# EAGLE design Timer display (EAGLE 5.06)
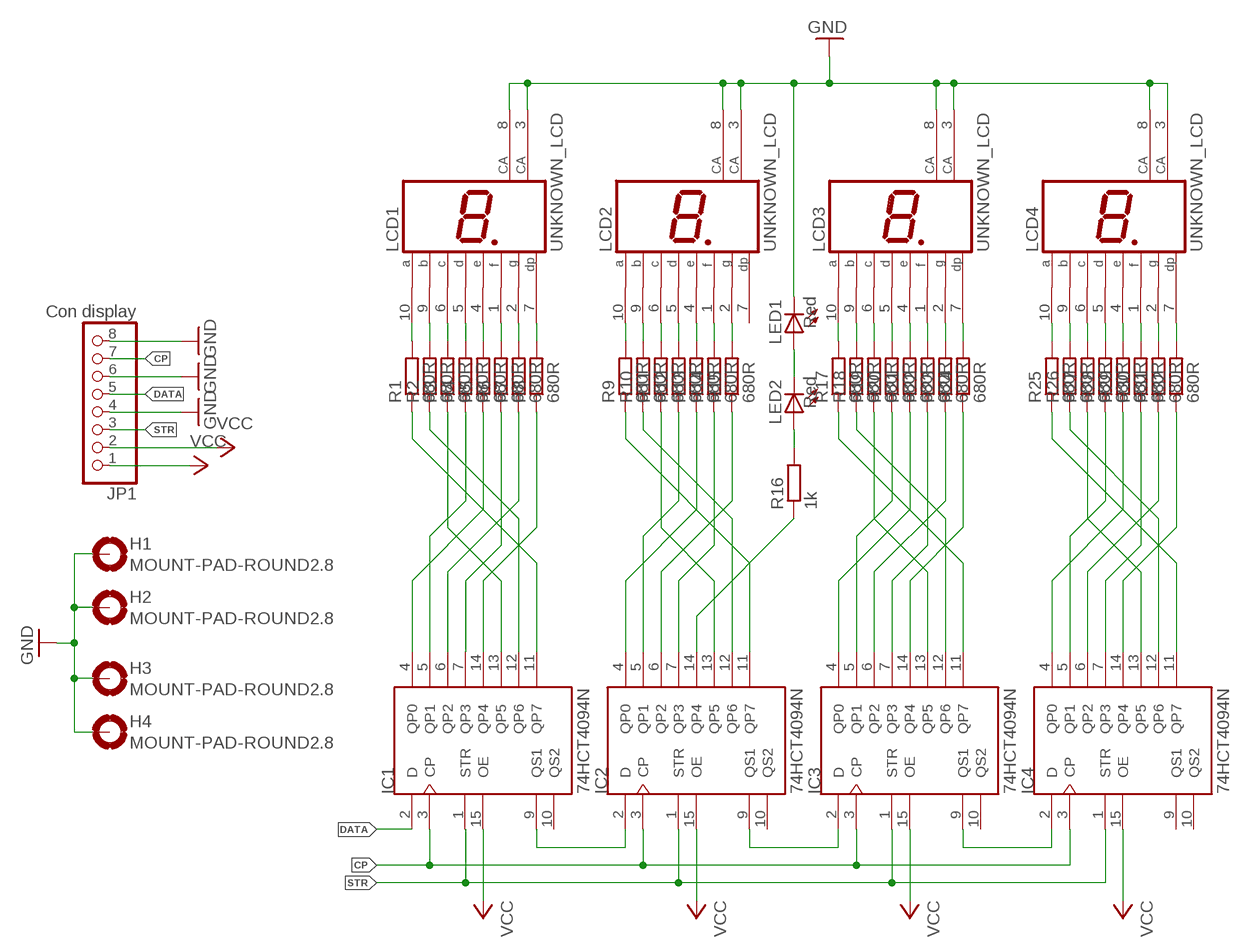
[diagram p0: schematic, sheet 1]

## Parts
H1  MOUNT-PAD-ROUND2.8  [2,8-PAD]
H2  MOUNT-PAD-ROUND2.8  [2,8-PAD]
H3  MOUNT-PAD-ROUND2.8  [2,8-PAD]
H4  MOUNT-PAD-ROUND2.8  [2,8-PAD]
IC1  74HCT4094N  [DIL16]
IC2  74HCT4094N  [DIL16]
IC3  74HCT4094N  [DIL16]
IC4  74HCT4094N  [DIL16]
JP1  Con display  PINHD-1X8  [1X08]
LCD1  UNKNOWN_LCD  [CA-MOJ]
LCD2  UNKNOWN_LCD  [CA-MOJ]
LCD3  UNKNOWN_LCD  [CA-MOJ]
LCD4  UNKNOWN_LCD  [CA-MOJ]
LED1  Red  LED3MM  [LED3MM]
LED2  Red  LED3MM  [LED3MM]
R1  680R  R-EU_R0805  [R0805]
R2  680R  R-EU_R0805  [R0805]
R3  680R  R-EU_R0805  [R0805]
R4  680R  R-EU_R0805  [R0805]
R5  680R  R-EU_R0805  [R0805]
R6  680R  R-EU_R0805  [R0805]
R7  680R  R-EU_R0805  [R0805]
R8  680R  R-EU_R0805  [R0805]
R9  680R  R-EU_R0805  [R0805]
R10  680R  R-EU_R0805  [R0805]
R11  680R  R-EU_R0805  [R0805]
R12  680R  R-EU_R0805  [R0805]
R13  680R  R-EU_R0805  [R0805]
R14  680R  R-EU_R0805  [R0805]
R15  680R  R-EU_R0805  [R0805]
R16  1k  R-EU_0207/10  [0207/10]
R17  680R  R-EU_R0805  [R0805]
R18  680R  R-EU_R0805  [R0805]
R19  680R  R-EU_R0805  [R0805]
R20  680R  R-EU_R0805  [R0805]
R21  680R  R-EU_R0805  [R0805]
R22  680R  R-EU_R0805  [R0805]
R23  680R  R-EU_R0805  [R0805]
R24  680R  R-EU_R0805  [R0805]
R25  680R  R-EU_R0805  [R0805]
R26  680R  R-EU_R0805  [R0805]
R27  680R  R-EU_R0805  [R0805]
R28  680R  R-EU_R0805  [R0805]
R29  680R  R-EU_R0805  [R0805]
R30  680R  R-EU_R0805  [R0805]
R31  680R  R-EU_R0805  [R0805]
R32  680R  R-EU_R0805  [R0805]

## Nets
CP: IC1.3(CP) IC2.3(CP) IC3.3(CP) IC4.3(CP) JP1.7
DATA: IC1.2(D) JP1.5
GND: H1.B2,8(MOUNT) H2.B2,8(MOUNT) H3.B2,8(MOUNT) H4.B2,8(MOUNT) JP1.4 JP1.6 JP1.8 LCD1.3(CA) LCD1.8(CA) LCD2.3(CA) LCD2.8(CA) LCD3.3(CA) LCD3.8(CA) LCD4.3(CA) LCD4.8(CA) LED1.K(C)
N$1: IC1.7(QP3) R6.1
N$2: LCD1.10(A) R1.2
N$3: LCD1.9(B) R2.2
N$4: LCD1.6(C) R3.2
N$5: LCD1.5(D) R4.2
N$6: LCD1.4(E) R5.2
N$7: LCD1.1(F) R6.2
N$8: LCD1.2(G) R7.2
N$9: LCD1.7(DP) R8.2
N$10: IC1.6(QP2) R7.1
N$11: IC1.4(QP0) R5.1
N$12: IC1.5(QP1) R4.1
N$13: IC1.11(QP7) R1.1
N$14: IC1.12(QP6) R2.1
N$15: IC1.14(QP4) R8.1
N$16: IC1.13(QP5) R3.1
N$17: IC2.11(QP7) R9.1
N$18: IC2.12(QP6) R10.1
N$19: IC2.13(QP5) R11.1
N$20: IC2.5(QP1) R12.1
N$21: IC2.4(QP0) R13.1
N$22: IC2.6(QP2) R15.1
N$23: IC2.7(QP3) R14.1
N$24: LED1.A LED2.K(C)
N$25: LED2.A R16.2
N$26: LCD2.2(G) R15.2
N$27: LCD2.1(F) R14.2
N$28: LCD2.4(E) R13.2
N$29: LCD2.5(D) R12.2
N$30: LCD2.6(C) R11.2
N$31: LCD2.9(B) R10.2
N$32: LCD2.10(A) R9.2
N$33: IC3.12(QP6) R18.1
N$34: IC3.11(QP7) R17.1
N$35: IC3.13(QP5) R19.1
N$36: IC3.5(QP1) R20.1
N$37: IC3.4(QP0) R21.1
N$38: IC3.6(QP2) R23.1
N$39: IC3.7(QP3) R22.1
N$40: IC3.14(QP4) R24.1
N$41: LCD3.10(A) R17.2
N$42: LCD3.9(B) R18.2
N$43: LCD3.6(C) R19.2
N$44: LCD3.5(D) R20.2
N$45: LCD3.4(E) R21.2
N$46: LCD3.1(F) R22.2
N$47: LCD3.2(G) R23.2
N$48: LCD3.7(DP) R24.2
N$49: LCD4.10(A) R25.2
N$50: LCD4.9(B) R26.2
N$51: LCD4.6(C) R27.2
N$52: LCD4.5(D) R28.2
N$53: LCD4.4(E) R29.2
N$54: LCD4.1(F) R30.2
N$55: LCD4.2(G) R31.2
N$56: LCD4.7(DP) R32.2
N$57: IC4.12(QP6) R26.1
N$58: IC4.11(QP7) R25.1
N$59: IC4.13(QP5) R27.1
N$61: IC4.4(QP0) R29.1
N$62: IC4.6(QP2) R31.1
N$63: IC4.7(QP3) R30.1
N$64: IC4.14(QP4) R32.1
N$65: IC2.14(QP4) R16.1
N$66: IC1.9(QS1) IC2.2(D)
N$67: IC4.5(QP1) R28.1
N$68: IC3.9(QS1) IC4.2(D)
N$75: IC2.9(QS1) IC3.2(D)
STR: IC1.1(STR) IC2.1(STR) IC3.1(STR) IC4.1(STR) JP1.3
VCC: IC1.15(OE) IC2.15(OE) IC3.15(OE) IC4.15(OE) JP1.1 JP1.2
Unconnected: IC1.10(QS2) IC2.10(QS2) IC3.10(QS2) IC4.9(QS1) IC4.10(QS2) LCD2.7(DP)

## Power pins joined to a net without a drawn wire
GND: IC1.8(GND) IC2.8(GND) IC3.8(GND) IC4.8(GND)
VCC: IC1.16(VCC) IC2.16(VCC) IC3.16(VCC) IC4.16(VCC)

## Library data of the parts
H1-H4 = holes:MOUNT-PAD-ROUND: MOUNTING PAD, round
IC1-IC4 = 74xx-eu:74*4094: 8-stage shift-and-store bus register
JP1 = pinhead:PINHD-1X8: PIN HEADER
LCD1-LCD4 = display-hp:UNKNOWN_LCD
LED1 LED2 = led:LED: LED
R1-R32 = resistor:R-EU_: RESISTOR, European symbol

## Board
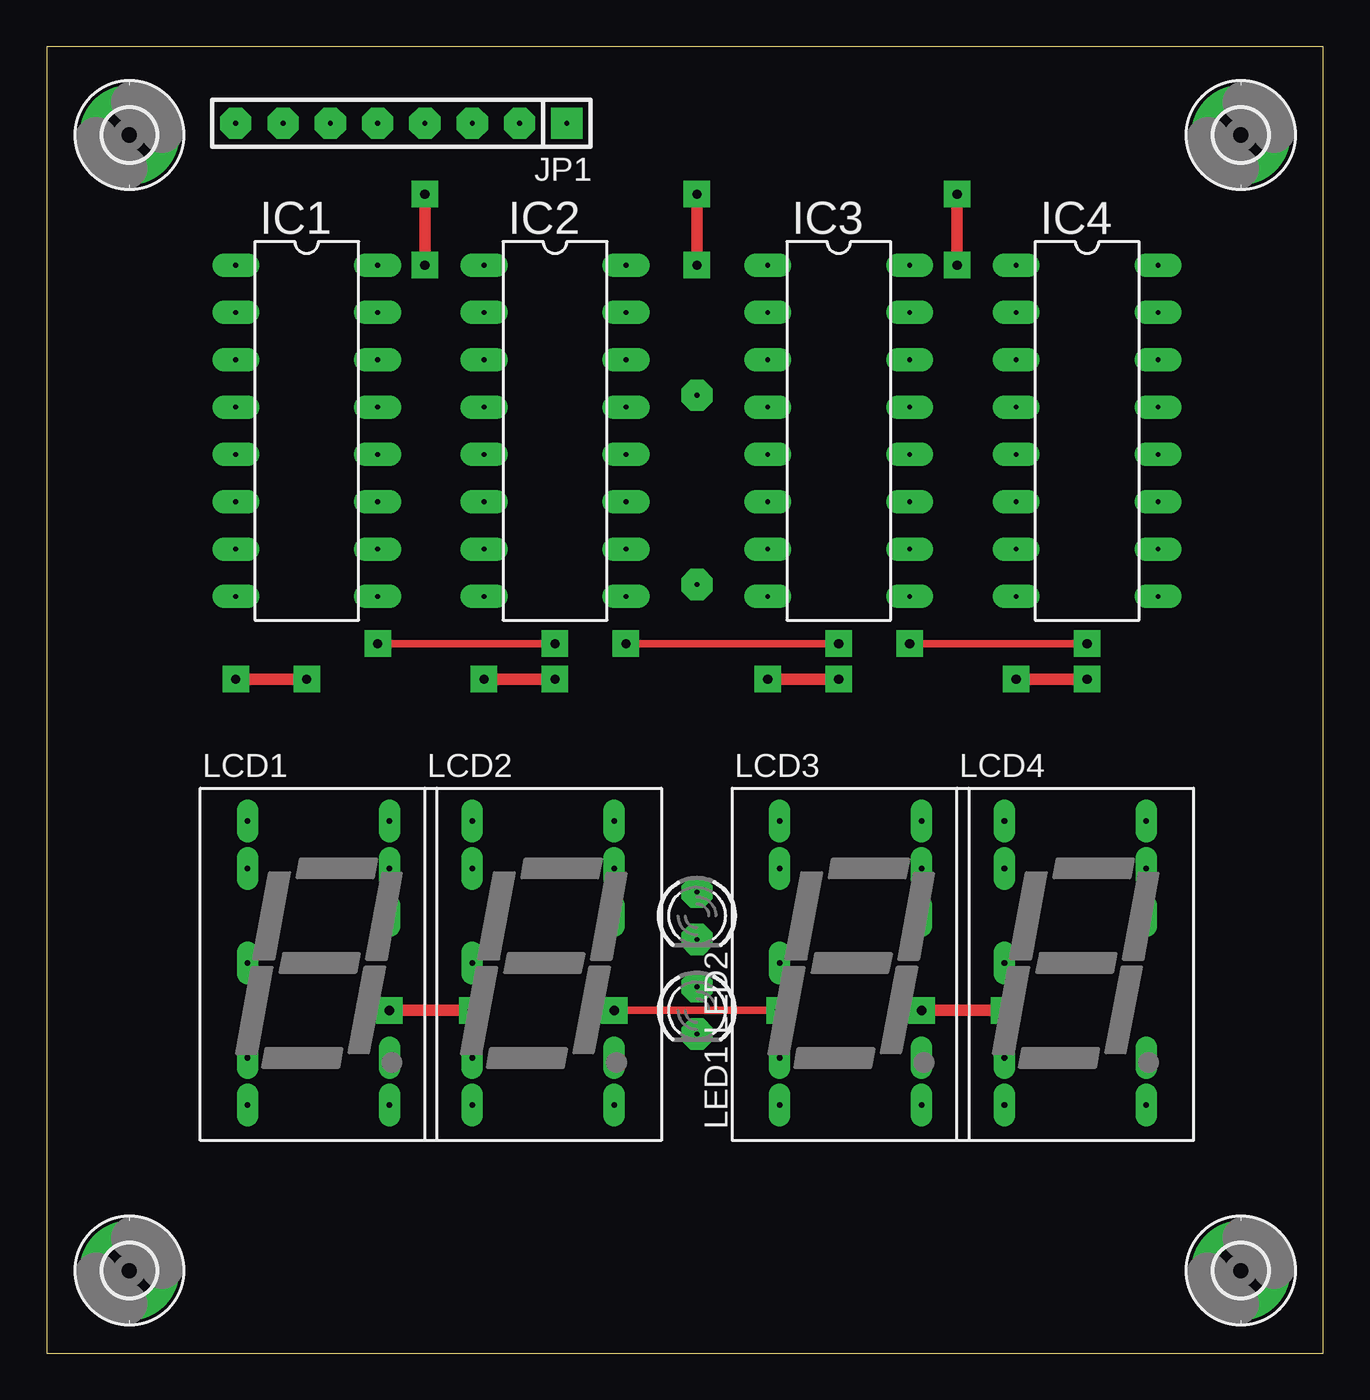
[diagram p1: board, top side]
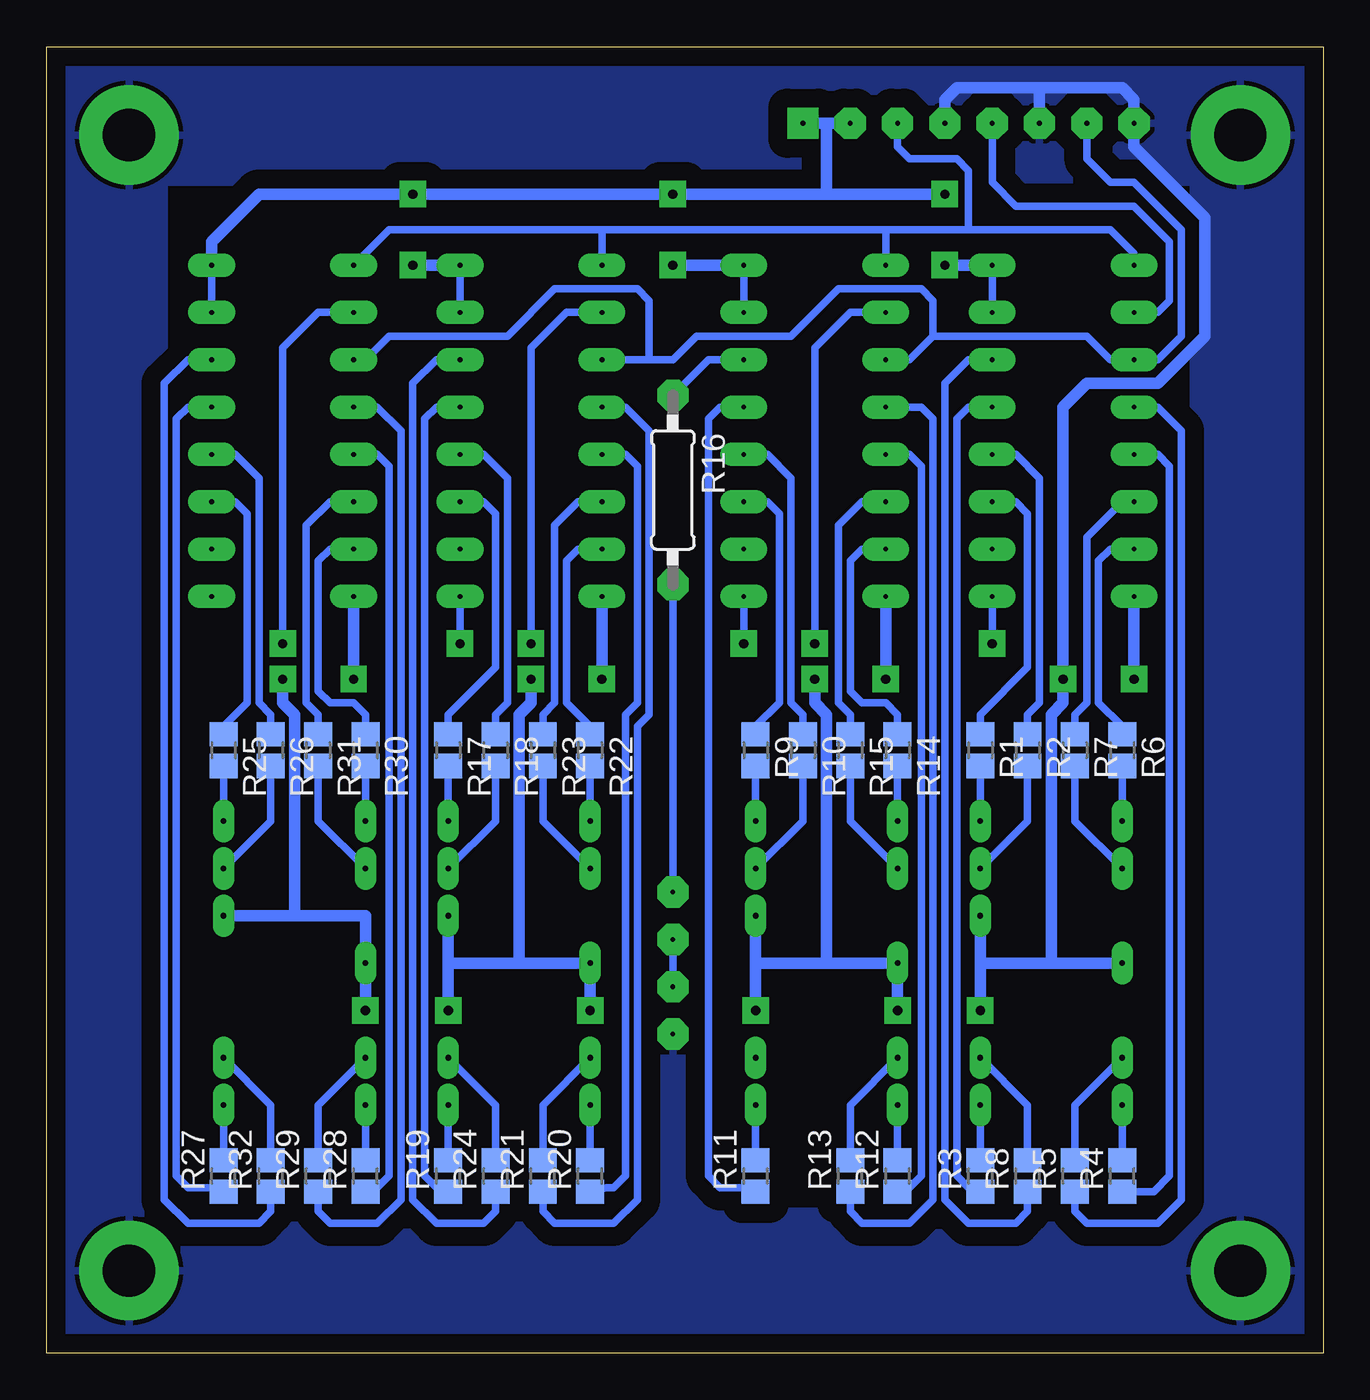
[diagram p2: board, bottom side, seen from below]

Size 68.56 x 70.16 mm. Coordinates in mm from the lower left corner, seen from the top.
Outline: 0,0 68.56,0 68.56,70.16 0,70.16 0,0
Copper layers (1*16): Top 0.035mm / dielectric 1.5mm / Bottom 0.035mm
Design rules "default *": minimum track width 16mil, minimum drill 1mil, track to track 8mil, track to pad 8mil, pad to pad 8mil, via to via 8mil, smd to smd 8mil, copper to edge 40mil, drill to drill 8mil, minimum pad ring 10mil, minimum via ring 8mil, stop-mask expansion 4mil, vias tented up to drill 0mil, thermal gap 10mil

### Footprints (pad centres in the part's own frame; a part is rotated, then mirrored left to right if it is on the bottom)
2,8-PAD = drill 2.8 pad 5.334 round: B2,8 0,0
DIL16 = drill 0.254 pad 1.27 long: 1 -8.89,-3.81; 2 -6.35,-3.81; 3 -3.81,-3.81; 4 -1.27,-3.81; 5 1.27,-3.81; 6 3.81,-3.81; 7 6.35,-3.81; 8 8.89,-3.81; 9 8.89,3.81; 10 6.35,3.81; 11 3.81,3.81; 12 1.27,3.81; 13 -1.27,3.81; 14 -3.81,3.81; 15 -6.35,3.81; 16 -8.89,3.81
1X08 = drill 0.254 pad 1.676 square: 1 -8.89,0 | drill 0.254 pad 1.676 octagon: 2 -6.35,0; 3 -3.81,0; 4 -1.27,0; 5 1.27,0; 6 3.81,0; 7 6.35,0; 8 8.89,0
CA-MOJ = drill 0.3 pad 1.143 long: 1 -6.35,8.89; 2 -6.35,6.35; 3 -6.35,1.27; 4 -6.35,-3.81; 5 -6.35,-6.35; 6 1.27,-6.35; 7 1.27,-3.81; 8 1.27,3.81; 9 1.27,6.35; 10 1.27,8.89
LED3MM = drill 0.254 pad 1.676 octagon: A -1.27,0; K 1.27,0
R0805 = smd 1.3 x 1.5: 1 -0.85,0; 2 0.85,0
0207/10 = drill 0.254 pad 1.676 octagon: 1 -5.08,0; 2 5.08,0

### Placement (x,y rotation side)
H1  4.45,4.44 0 top
H2  64.13,4.44 0 top
H3  64.13,65.41 0 top
H4  4.45,65.41 0 top
IC1  13.97,49.53 270 top
IC2  27.31,49.53 270 top
IC3  42.55,49.53 270 top
IC4  55.88,49.53 270 top
JP1  19.05,66.04 180 top
LCD1  17.14,19.68 0 top
LCD2  29.21,19.68 0 top
LCD3  45.72,19.68 0 top
LCD4  57.78,19.68 0 top
LED1  34.92,18.41 270 top
LED2  34.92,23.49 270 top
R1  18.41,32.38 270 bottom
R2  15.88,32.38 270 bottom
R3  18.41,9.53 90 bottom
R4  10.8,9.53 90 bottom
R5  13.34,9.53 90 bottom
R6  10.8,32.38 270 bottom
R7  13.34,32.38 270 bottom
R8  15.88,9.53 90 bottom
R9  30.48,32.38 270 bottom
R10  27.94,32.38 270 bottom
R11  30.48,9.53 90 bottom
R12  22.86,9.53 90 bottom
R13  25.4,9.53 90 bottom
R14  22.86,32.38 270 bottom
R15  25.4,32.38 270 bottom
R16  34.92,46.35 270 bottom
R17  46.99,32.38 270 bottom
R18  44.45,32.38 270 bottom
R19  46.99,9.53 90 bottom
R20  39.37,9.53 90 bottom
R21  41.91,9.53 90 bottom
R22  39.37,32.38 270 bottom
R23  41.91,32.38 270 bottom
R24  44.45,9.53 90 bottom
R25  59.05,32.38 270 bottom
R26  56.52,32.38 270 bottom
R27  59.05,9.53 90 bottom
R28  51.44,9.53 90 bottom
R29  53.97,9.53 90 bottom
R30  51.44,32.38 270 bottom
R31  53.97,32.38 270 bottom
R32  56.52,9.53 90 bottom

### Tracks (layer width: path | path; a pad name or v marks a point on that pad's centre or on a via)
CP
  Bottom 0.406: IC4.3 51.44,53.34 50.17,54.61 43.81,54.61 41.28,57.15 36.83,57.15 36.2,56.52 36.2,53.34 | 36.2,53.34 IC3.3 | 36.2,53.34 34.92,53.34 33.66,54.61 28.57,54.61 26.04,57.15 21.59,57.15 20.96,56.52 20.96,54.61 | JP1.7 12.7,64.14 11.43,62.86 10.16,62.86 7.62,60.32 7.62,54.61 8.89,53.34 IC1.3 11.43,53.34 12.7,54.61 20.96,54.61 | IC2.3 22.22,53.34 20.96,54.61
DATA
  Bottom 0.406: IC1.2 8.89,55.88 8.25,56.52 8.25,59.69 10.16,61.59 16.51,61.59 17.78,62.86 JP1.5
GND  (via drill 0.5 pad 1.42)
  Top 0.406: v30.48,18.41 v39.37,18.41
  Top 0.61: v27.31,36.2 v23.5,36.2 | v46.99,18.41 v51.44,18.41 | v55.88,36.2 v52.07,36.2 | v18.41,18.41 v22.86,18.41 | v42.55,36.2 v38.73,36.2 | v13.97,36.2 v10.16,36.2
  Bottom 0.61: v23.5,36.2 IC2.8 | 46.99,20.95 v46.99,18.41 | 46.99,20.95 LCD3.8 | v51.44,18.41 51.44,23.49 | 51.44,23.49 55.24,23.49 | 55.24,23.49 LCD4.8 | 51.44,23.49 LCD4.3 | v52.07,36.2 IC4.8 | 43.18,20.95 LCD3.3 v39.37,18.41 | 30.48,20.95 v30.48,18.41 | 30.48,20.95 LCD2.8 | v38.73,36.2 IC3.8 | v10.16,36.2 IC1.8 | 15.24,67.94 10.8,67.94 10.16,67.31 JP1.8 10.16,64.77 6.35,60.96 6.35,54.61 8.89,52.07 12.7,52.07 13.97,50.8 v13.97,36.2 13.97,34.92 14.61,34.29 14.61,20.95 | 15.24,67.94 19.68,67.94 20.32,67.31 JP1.4 | 15.24,67.94 JP1.6 | LCD1.3 14.61,20.95 | 14.61,20.95 18.41,20.95 | 18.41,20.95 v18.41,18.41 | 18.41,20.95 LCD1.8 | v22.86,18.41 LCD2.3 26.67,20.95 | 26.67,20.95 30.48,20.95 | 43.18,20.95 46.99,20.95 | 43.18,20.95 43.18,34.29 42.55,34.92 v42.55,36.2 | 55.24,23.49 55.24,34.29 55.88,34.92 v55.88,36.2 | 26.67,20.95 26.67,34.29 27.31,34.92 v27.31,36.2
  pour Bottom (isolate 1.016): 62.86,62.86 6.98,62.86 6.98,7.62 -0.63,7.62 -0.63,70.48 62.86,70.48
  pour Bottom (isolate 1.016): 62.23,70.48 69.22,70.48 69.22,-0.64 0,-0.64 0,7.62 33.02,7.62 33.02,18.41 36.83,18.41 36.83,7.62 62.23,7.62
N$1
  Bottom 0.406: IC1.7 11.43,43.18 12.07,42.55 12.07,34.92 10.8,33.66 R6.1
N$2
  Bottom 0.406: LCD1.10 R1.2
N$3
  Bottom 0.406: R2.2 15.88,28.57 LCD1.9
N$4
  Bottom 0.406: R3.2 LCD1.6
N$5
  Bottom 0.406: R4.2 LCD1.5
N$6
  Bottom 0.406: R5.2 13.34,13.34 LCD1.4
N$7
  Bottom 0.406: LCD1.1 R6.2
N$8
  Bottom 0.406: R7.2 13.34,28.57 LCD1.2
N$9
  Bottom 0.406: R8.2 15.88,13.34 LCD1.7
N$10
  Bottom 0.406: IC1.6 10.8,45.72 12.7,43.81 12.7,34.92 13.34,34.29 R7.1
N$11
  Bottom 0.406: IC1.4 8.89,50.8 7.62,49.53 7.62,8.26 8.89,6.99 12.7,6.99 13.34,7.62 R5.1
N$12
  Bottom 0.406: IC1.5 8.89,48.26 8.25,47.62 8.25,9.53 9.11,8.68 R4.1
N$13
  Bottom 0.406: IC1.11 16.51,45.72 15.88,45.09 15.88,36.83 18.41,34.29 R1.1
N$14
  Bottom 0.406: IC1.12 16.51,48.26 15.24,46.99 15.24,34.92 15.88,34.29 R2.1
N$15
  Bottom 0.406: IC1.14 19.05,53.34 20.32,52.07 20.32,8.26 19.05,6.99 16.51,6.99 15.88,7.62 R8.1
N$16
  Bottom 0.406: IC1.13 19.05,50.8 19.68,50.16 19.68,9.53 19.05,8.89 18.63,8.89 R3.1
N$17
  Bottom 0.406: IC2.11 29.85,45.72 29.21,45.09 29.21,34.92 30.48,33.66 R9.1
N$18
  Bottom 0.406: IC2.12 29.85,48.26 28.57,46.99 28.57,34.92 27.94,34.29 R10.1
N$19
  Bottom 0.406: IC2.13 32.39,50.8 33.02,50.16 33.02,9.53 32.39,8.89 30.7,8.89 R11.1 30.9,8.26
N$20
  Bottom 0.406: IC2.5 22.22,48.26 21.59,47.62 21.59,9.53 22.22,8.89 22.64,8.89 R12.1
N$21
  Bottom 0.406: IC2.4 21.59,50.8 20.96,50.16 20.96,8.26 22.22,6.99 24.77,6.99 25.4,7.62 R13.1
N$22
  Bottom 0.406: IC2.6 24.77,45.72 26.04,44.45 26.04,34.92 25.4,34.29 R15.1
N$23
  Bottom 0.406: IC2.7 24.77,43.18 25.4,42.55 25.4,35.56 24.77,34.92 23.5,34.92 22.86,34.29 R14.1 22.86,33.66
N$24
  Bottom 0.406: LED1.A LED2.K
N$25
  Bottom 0.406: LED2.A R16.2
N$26
  Bottom 0.406: R15.2 25.4,28.57 LCD2.2
N$27
  Bottom 0.406: LCD2.1 R14.2
N$28
  Bottom 0.406: R13.2 25.4,13.34 LCD2.4
N$29
  Bottom 0.406: R12.2 LCD2.5
N$30
  Bottom 0.406: R11.2 LCD2.6
N$31
  Bottom 0.406: R10.2 27.94,28.57 LCD2.9
N$32
  Bottom 0.406: LCD2.10 R9.2
N$33
  Bottom 0.406: IC3.12 45.08,48.26 43.81,46.99 43.81,34.92 44.45,34.29 R18.1
N$34
  Bottom 0.406: IC3.11 45.08,45.72 44.45,45.09 44.45,36.83 46.99,34.29 R17.1
N$35
  Bottom 0.406: IC3.13 47.62,50.8 48.26,50.16 48.26,9.53 47.62,8.89 47.2,8.89 R19.1
N$36
  Bottom 0.406: IC3.5 37.47,48.26 36.83,47.62 36.83,34.92 37.47,34.29 37.47,9.53 38.1,8.89 38.52,8.89 R20.1
N$37
  Bottom 0.406: IC3.4 37.47,50.8 36.2,49.53 36.2,34.29 36.83,33.66 36.83,8.26 38.1,6.99 41.28,6.99 41.91,7.62 R21.1
N$38
  Bottom 0.406: IC3.6 40,45.72 41.28,44.45 41.28,34.92 41.91,34.29 R23.1
N$39
  Bottom 0.406: IC3.7 40,43.18 40.64,42.55 40.64,34.92 39.37,33.66 R22.1
N$40
  Bottom 0.406: IC3.14 47.62,53.34 48.89,52.07 48.89,8.26 47.62,6.99 45.08,6.99 44.45,7.62 R24.1
N$41
  Bottom 0.406: LCD3.10 R17.2
N$42
  Bottom 0.406: R18.2 44.45,28.57 LCD3.9
N$43
  Bottom 0.406: R19.2 LCD3.6
N$44
  Bottom 0.406: R20.2 LCD3.5
N$45
  Bottom 0.406: R21.2 41.91,13.34 LCD3.4
N$46
  Bottom 0.406: LCD3.1 R22.2
N$47
  Bottom 0.406: R23.2 41.91,28.57 LCD3.2
N$48
  Bottom 0.406: R24.2 44.45,13.34 LCD3.7
N$49
  Bottom 0.406: LCD4.10 R25.2
N$50
  Bottom 0.406: R26.2 56.52,28.57 LCD4.9
N$51
  Bottom 0.406: R27.2 LCD4.6
N$52
  Bottom 0.406: R28.2 LCD4.5
N$53
  Bottom 0.406: R29.2 53.97,13.34 LCD4.4
N$54
  Bottom 0.406: LCD4.1 R30.2
N$55
  Bottom 0.406: R31.2 53.97,28.57 LCD4.2
N$56
  Bottom 0.406: R32.2 56.52,13.34 LCD4.7
N$57
  Bottom 0.406: IC4.12 58.42,48.26 57.15,46.99 57.15,34.92 56.52,34.29 R26.1
N$58
  Bottom 0.406: IC4.11 58.42,45.72 57.78,45.09 57.78,34.92 59.05,33.66 R25.1
N$59
  Bottom 0.406: IC4.13 60.96,50.8 61.59,50.16 61.59,9.53 60.96,8.89 59.27,8.89 R27.1
N$61
  Bottom 0.406: IC4.4 50.8,50.8 49.53,49.53 49.53,8.26 50.8,6.99 53.34,6.99 53.97,7.62 R29.1
N$62
  Bottom 0.406: IC4.6 53.34,45.72 54.61,44.45 54.61,34.92 53.97,34.29 R31.1
N$63
  Bottom 0.406: IC4.7 53.34,43.18 53.97,42.55 53.97,35.56 53.34,34.92 52.07,34.92 51.44,34.29 R30.1 51.44,33.66
N$64
  Bottom 0.406: IC4.14 60.96,53.34 62.23,52.07 62.23,8.26 60.96,6.99 57.15,6.99 56.52,7.62 R32.1
N$65
  Bottom 0.406: IC2.14 33.02,53.34 R16.1
N$66  (via drill 0.5 pad 1.42)
  Top 0.406: v17.78,38.1 v27.31,38.1
  Bottom 0.406: v17.78,38.1 IC1.9 | v27.31,38.1 27.31,53.98 25.4,55.88 IC2.2
N$67
  Bottom 0.406: IC4.5 50.8,48.26 50.17,47.62 50.17,9.53 50.8,8.89 51.22,8.89 R28.1
N$68  (via drill 0.5 pad 1.42)
  Top 0.406: v46.36,38.1 v55.88,38.1
  Bottom 0.406: v46.36,38.1 IC3.9 | v55.88,38.1 55.88,53.98 53.97,55.88 IC4.2
N$75  (via drill 0.5 pad 1.42)
  Top 0.406: v31.11,38.1 v42.55,38.1
  Bottom 0.406: v42.55,38.1 42.55,53.98 40.64,55.88 IC3.2 | v31.11,38.1 IC2.9
STR
  Bottom 0.406: 23.5,60.32 38.73,60.32 | 38.73,60.32 50.17,60.32 IC4.1 | 38.73,60.32 IC3.1 | 23.5,60.32 IC2.1 | IC1.1 10.16,59.05 11.43,60.32 19.05,60.32 | 19.05,60.32 23.5,60.32 | 19.05,60.32 19.05,63.5 19.68,64.14 22.22,64.14 22.86,64.77 JP1.3
VCC  (via drill 0.5 pad 1.42)
  Top 0.61: v34.92,62.23 v34.92,58.42 | v48.89,62.23 v48.89,58.42 | v20.32,58.42 v20.32,62.23
  Bottom 0.406: IC1.15 IC1.16 | IC2.16 IC2.15 | IC3.16 IC3.15 | IC4.16 IC4.15
  Bottom 0.61: v34.92,58.42 IC2.16 | v48.89,58.42 IC3.16 | IC4.16 59.69,59.69 57.15,62.23 v48.89,62.23 v34.92,62.23 26.67,62.23 | IC1.16 v20.32,58.42 | 26.67,66.04 JP1.2 | 26.67,66.04 JP1.1 | v20.32,62.23 26.67,62.23 | 26.67,62.23 26.67,66.04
